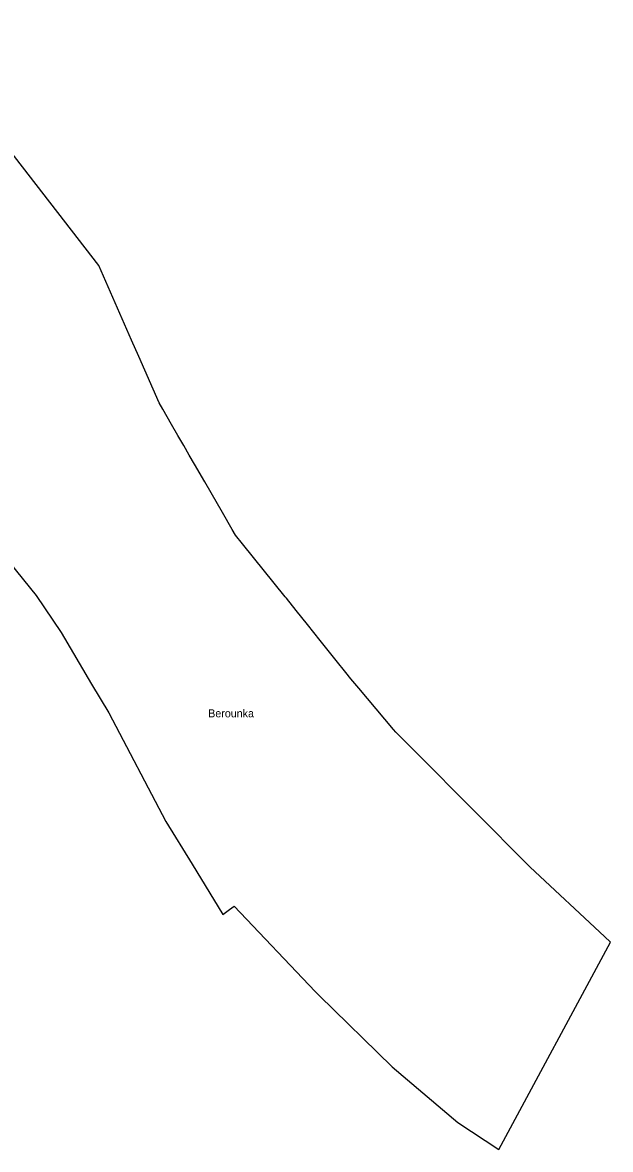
# Model space of a CAD drawing. Extents: x -762274 to -759271, y -1061928 to -1059060.
# Drawn here: x -759521.4 to -759271.4, y -1059969.2 to -1059490.4 of the extents above; entities that cross this region are included whole.
import ezdxf

# ---------------------------------------------------------------- set-up
doc = ezdxf.new("R2010")
doc.units = 0
for name, color, linetype in [('Hranice parcel', 7, 'Continuous'), ('Polygon ku', 7, 'Continuous'), ('Polygon parcely', 7, 'Continuous'), ('Pop  PČ popisy', 7, 'Continuous')]:
    doc.layers.add(name, color=color, linetype=linetype)

msp = doc.modelspace()

# ---------------------------------------------------------------- linework, layer by layer
at = {"layer": 'Hranice parcel'}
for p, q in [((-759475.04, -1059625.36), (-759488.97, -1059593.62)), ((-759471.96, -1059632.37), (-759475.04, -1059625.36)), ((-759463.34, -1059652.01), (-759471.96, -1059632.37)), ((-759461.76, -1059654.74), (-759463.34, -1059652.01)), ((-759458.04, -1059661.17), (-759461.76, -1059654.74)), ((-759455.33, -1059665.85), (-759458.04, -1059661.17)), ((-759452.9, -1059670.05), (-759455.33, -1059665.85)), ((-759450.52, -1059674.17), (-759452.9, -1059670.05)), ((-759448.24, -1059678.1), (-759450.52, -1059674.17)), ((-759443.91, -1059685.59), (-759448.24, -1059678.1)), ((-759441.18, -1059690.29), (-759443.91, -1059685.59)), ((-759436.38, -1059698.6), (-759441.18, -1059690.29)), ((-759432.24, -1059705.75), (-759436.38, -1059698.6)), ((-759409.7, -1059734.4), (-759427.88, -1059711.85)), ((-759515.68, -1059733.83), (-759504.93, -1059749.61)), ((-759409.2, -1059735.02), (-759409.7, -1059734.4)), ((-759405.09, -1059740.15), (-759409.2, -1059735.02)), ((-759400.23, -1059746.21), (-759405.09, -1059740.15)), ((-759394.87, -1059752.9), (-759400.23, -1059746.21)), ((-759504.93, -1059749.61), (-759492.16, -1059771.53)), ((-759387.99, -1059761.48), (-759394.87, -1059752.9)), ((-759383.91, -1059766.57), (-759387.99, -1059761.48)), ((-759492.16, -1059771.53), (-759484.76, -1059783.65)), ((-759363.62, -1059790.8), (-759378.37, -1059773.28)), ((-759484.76, -1059783.65), (-759460.48, -1059829.83)), ((-759305.52, -1059849.32), (-759354.05, -1059800.58)), ((-759460.48, -1059829.83), (-759449.31, -1059848.06)), ((-759449.31, -1059848.06), (-759436.27, -1059869.34)), ((-759318.9, -1059969.2), (-759271.37, -1059881.09)), ((-759396.97, -1059902.04), (-759395.3, -1059903.8)), ((-759395.3, -1059903.8), (-759364.2, -1059934.1))]:
    msp.add_line(p, q, dxfattribs=at)
for points in [[(-759488.97, -1059593.62), (-759527.2, -1059544.18), (-759566.44, -1059504.15), (-759588.8, -1059485.7)], [(-759595.54, -1059635.84), (-759578.31, -1059655.86), (-759561.4, -1059677.61), (-759540.36, -1059702.99), (-759523.98, -1059723.53), (-759515.68, -1059733.83)], [(-759427.88, -1059711.85), (-759430.79, -1059708.25), (-759432.24, -1059705.75)], [(-759378.37, -1059773.28), (-759381.8, -1059769.2), (-759383.91, -1059766.57)], [(-759354.05, -1059800.58), (-759362.7, -1059791.9), (-759363.62, -1059790.8)], [(-759271.37, -1059881.09), (-759273.93, -1059878.71), (-759305.52, -1059849.32)], [(-759436.27, -1059869.34), (-759433.4, -1059867.32), (-759431.4, -1059865.9), (-759396.97, -1059902.04)], [(-759364.2, -1059934.1), (-759336.25, -1059957.8), (-759318.9, -1059969.2)]]:
    msp.add_lwpolyline(points, dxfattribs=at)
at = {"layer": 'Polygon ku'}
msp.add_lwpolyline([(-759523.98, -1059723.53), (-759515.68, -1059733.83), (-759504.93, -1059749.61), (-759492.16, -1059771.53), (-759484.76, -1059783.65), (-759460.48, -1059829.83), (-759449.31, -1059848.06), (-759436.27, -1059869.34), (-759433.4, -1059867.32), (-759431.4, -1059865.9), (-759396.97, -1059902.04), (-759395.3, -1059903.8), (-759364.2, -1059934.1), (-759336.25, -1059957.8), (-759318.9, -1059969.2), (-759271.37, -1059881.09), (-759273.93, -1059878.71), (-759305.52, -1059849.32), (-759354.05, -1059800.58), (-759362.7, -1059791.9), (-759363.62, -1059790.8), (-759378.37, -1059773.28), (-759381.8, -1059769.2), (-759383.91, -1059766.57), (-759387.99, -1059761.48), (-759394.87, -1059752.9), (-759400.23, -1059746.21), (-759405.09, -1059740.15), (-759409.2, -1059735.02), (-759409.7, -1059734.4), (-759427.88, -1059711.85), (-759430.79, -1059708.25), (-759432.24, -1059705.75), (-759436.38, -1059698.6), (-759441.18, -1059690.29), (-759443.91, -1059685.59), (-759448.24, -1059678.1), (-759450.52, -1059674.17), (-759452.9, -1059670.05), (-759455.33, -1059665.85), (-759458.04, -1059661.17), (-759461.76, -1059654.74), (-759463.34, -1059652.01), (-759471.96, -1059632.37), (-759475.04, -1059625.36), (-759488.97, -1059593.62), (-759527.2, -1059544.18)], dxfattribs=at)
at = {"layer": 'Polygon parcely'}
msp.add_lwpolyline([(-759523.98, -1059723.53), (-759515.68, -1059733.83), (-759504.93, -1059749.61), (-759492.16, -1059771.53), (-759484.76, -1059783.65), (-759460.48, -1059829.83), (-759449.31, -1059848.06), (-759436.27, -1059869.34), (-759433.4, -1059867.32), (-759431.4, -1059865.9), (-759396.97, -1059902.04), (-759395.3, -1059903.8), (-759364.2, -1059934.1), (-759336.25, -1059957.8), (-759318.9, -1059969.2), (-759271.37, -1059881.09), (-759273.93, -1059878.71), (-759305.52, -1059849.32), (-759354.05, -1059800.58), (-759362.7, -1059791.9), (-759363.62, -1059790.8), (-759378.37, -1059773.28), (-759381.8, -1059769.2), (-759383.91, -1059766.57), (-759387.99, -1059761.48), (-759394.87, -1059752.9), (-759400.23, -1059746.21), (-759405.09, -1059740.15), (-759409.2, -1059735.02), (-759409.7, -1059734.4), (-759427.88, -1059711.85), (-759430.79, -1059708.25), (-759432.24, -1059705.75), (-759436.38, -1059698.6), (-759441.18, -1059690.29), (-759443.91, -1059685.59), (-759448.24, -1059678.1), (-759450.52, -1059674.17), (-759452.9, -1059670.05), (-759455.33, -1059665.85), (-759458.04, -1059661.17), (-759461.76, -1059654.74), (-759463.34, -1059652.01), (-759471.96, -1059632.37), (-759475.04, -1059625.36), (-759488.97, -1059593.62), (-759527.2, -1059544.18)], dxfattribs=at)

# ---------------------------------------------------------------- texts
at = {"layer": 'Pop  PČ popisy'}
msp.add_text('Berounka', height=3.4, dxfattribs=at).set_placement((-759442.46, -1059785.6))

doc.saveas('drawing.dxf')
